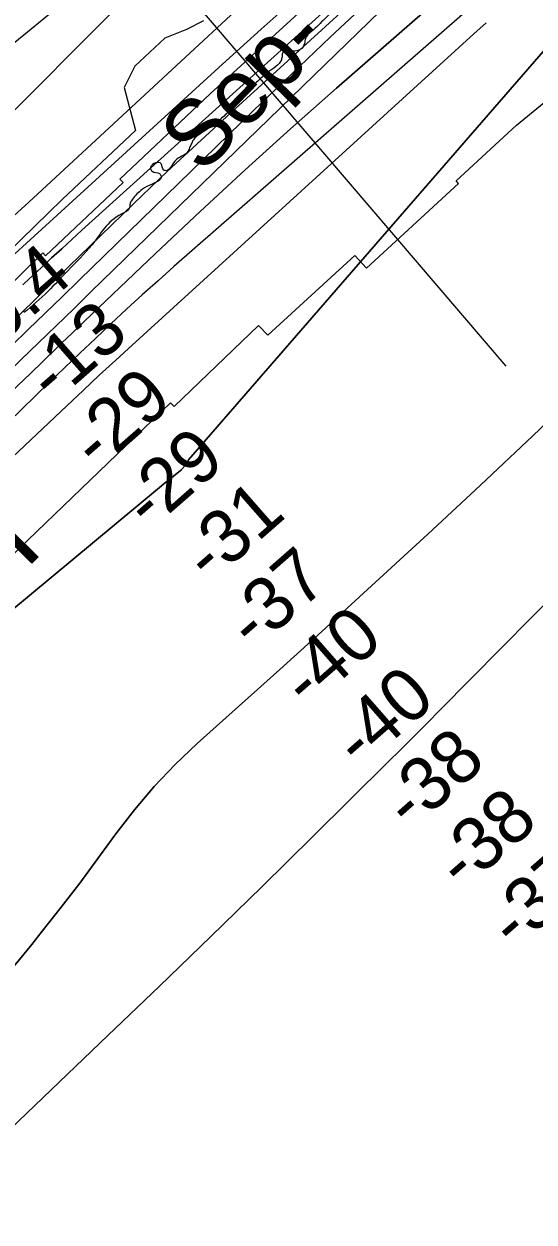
# Model space of a CAD drawing. Extents: x 3419139 to 3457078, y 540382 to 565875.
# Drawn here: x 3451925 to 3452566, y 547868 to 549375 of the extents above; entities that cross this region are included whole.
import ezdxf

# ---------------------------------------------------------------- set-up
doc = ezdxf.new("R2010")
doc.units = 0
for name, color, linetype in [('V-RIVR-EDGE', 7, 'Continuous'), ('V-RIVR-IDEN', 7, 'Continuous'), ('V-RIVR-RANG', 7, 'Continuous'), ('V-RRAP-RVMT', 7, 'Continuous'), ('V-RRAP-RVMT-IDEN', 7, 'Continuous'), ('V-SITE-VEGE', 7, 'Continuous'), ('V-TOPO-DPTH', 7, 'Continuous'), ('V-TOPO-MINR', 7, 'Continuous'), ('V-TOPO-WATR', 7, 'Continuous'), ('V-WETL-SWMP', 7, 'Continuous')]:
    doc.layers.add(name, color=color, linetype=linetype)

msp = doc.modelspace()

# ---------------------------------------------------------------- linework, layer by layer
at = {"layer": 'V-RIVR-EDGE'}
msp.add_spline([(3452565, 549632.1), (3452565.8, 549625.9), (3452563.7, 549618.5), (3452554.6, 549606.1), (3452547.2, 549600.4), (3452538.9, 549595.9), (3452524.5, 549586.4), (3452523.6, 549582.7), (3452524.4, 549578.2), (3452515.8, 549570.4), (3452499.6, 549558.9), (3452491, 549550.6), (3452475.2, 549530), (3452462.9, 549521.8), (3452457.1, 549517.3), (3452450, 549512.4), (3452445.1, 549511.1), (3452443.9, 549509.1), (3452445.1, 549506.2), (3452435.2, 549495.9), (3452420.7, 549482.3), (3452414.1, 549476.2), (3452409.5, 549472.9), (3452405.8, 549470), (3452404.2, 549467.9), (3452400, 549461.4), (3452394.6, 549457.7), (3452387.6, 549454.8), (3452379.8, 549447), (3452351.7, 549422.3), (3452344.2, 549414.5), (3452341.3, 549414.5), (3452336.8, 549417.4), (3452332.7, 549417.4), (3452327.3, 549414.9), (3452324.8, 549411.6), (3452327.3, 549406.3), (3452327.3, 549403), (3452324.8, 549400.1), (3452317.4, 549393.9), (3452303.3, 549381.2), (3452286.8, 549365.5), (3452278.9, 549356.5), (3452277.7, 549350.3), (3452273.1, 549342.9), (3452262.8, 549340.4), (3452255, 549340.1), (3452250.4, 549338.8), (3452249.6, 549334.7), (3452248.7, 549329.8), (3452231.8, 549314.1), (3452217.3, 549301.4), (3452203.7, 549290.3), (3452185.5, 549268.1), (3452173.5, 549256.1), (3452162.4, 549247.1), (3452149.5, 549238.5), (3452142.5, 549233.5), (3452138, 549229), (3452135.9, 549224.9), (3452133.8, 549220.3), (3452131.3, 549214.6), (3452114.8, 549202.2), (3452102.4, 549190.3), (3452100.8, 549191.1), (3452097.5, 549199), (3452094.6, 549200.6), (3452086.8, 549198.2), (3452084.3, 549194.5), (3452084.3, 549192.8), (3452086.3, 549189.5), (3452095.4, 549186.6), (3452097.4, 549183.3), (3452082.6, 549171.8), (3452071.8, 549165.2), (3452060.3, 549152.5), (3452058.2, 549147.9), (3452057.8, 549143.8), (3452047.4, 549135.6), (3452010.6, 549096.9), (3451980, 549064.4), (3451955.2, 549038.5), (3451925, 549011.8)], degree=3, dxfattribs=at)
at = {"layer": 'V-RIVR-RANG'}
msp.add_line((3451920.2, 549659), (3452531, 548944.4), dxfattribs=at)
at = {"layer": 'V-RRAP-RVMT'}
for p, q in [((3452279.9, 549397.3), (3452159.3, 549286.7)), ((3452544.5, 549247.3), (3452684.8, 549364)), ((3452159.3, 549286.7), (3452045.7, 549179.8)), ((3452468.6, 549177.6), (3452544.5, 549247.3)), ((3452045.7, 549179.8), (3452049.8, 549175.4)), ((3452471.5, 549174), (3452468.6, 549177.6)), ((3452049.8, 549175.4), (3451952.3, 549083.3)), ((3452355.7, 549067.6), (3452471.5, 549174)), ((3451948.9, 549086.9), (3451634.9, 548778.5)), ((3451952.3, 549083.3), (3451948.9, 549086.9)), ((3452231.6, 548983.5), (3452341.2, 549083.6)), ((3452341.2, 549083.6), (3452355.7, 549067.6)), ((3452114, 548893.7), (3452220, 548995.4)), ((3452220, 548995.4), (3452231.6, 548983.5)), ((3451907.2, 548704), (3452109.3, 548898.4)), ((3452109.3, 548898.4), (3452114, 548893.7))]:
    msp.add_line(p, q, dxfattribs=at)
at = {"layer": 'V-SITE-VEGE'}
msp.add_lwpolyline([(3452150.8, 549378.5), (3452129.3, 549367.7), (3452102.3, 549356.9), (3452064.5, 549321.8), (3452051, 549294.8), (3452065.3, 549240.7), (3451973.5, 549154.4), (3451852.5, 549036.7)], dxfattribs=at)
at = {"layer": 'V-TOPO-DPTH'}
for points in [[(3451923.7, 549046.7), (3451925.4, 549048.2), (3451947.2, 549068.7), (3451959.8, 549080.5), (3451972.5, 549092.2), (3451985.2, 549103.9), (3451997.9, 549115.5), (3452460, 549533.4)], [(3451909.4, 548912.4), (3451932.7, 548934.9), (3451966.2, 548967.3), (3451972.6, 548973.6), (3451979.1, 548979.8), (3451985.5, 548985.9), (3451992, 548992.1), (3452090.4, 549086.2), (3452146.5, 549139.1), (3452203, 549191.4), (3452260.3, 549243), (3452317.9, 549294.1), (3452505.1, 549457.4)], [(3452505.1, 549457.4), (3452317.9, 549294.1), (3452260.3, 549243), (3452203, 549191.4), (3452146.5, 549139.1), (3452090.4, 549086.2), (3451992, 548992.1), (3451985.5, 548985.9), (3451979.1, 548979.8), (3451972.6, 548973.6), (3451966.2, 548967.3), (3451932.7, 548934.9), (3451909.4, 548912.4)], [(3451909.1, 548969.6), (3451930.4, 548990.4), (3451951.7, 549011.1), (3451973, 549031.8), (3451994.3, 549052.5), (3452213.6, 549265.8), (3452261.7, 549312.2), (3452310.2, 549358.2), (3452359.1, 549403.9)], [(3452359.1, 549403.9), (3452310.2, 549358.2), (3452261.7, 549312.2), (3452213.6, 549265.8), (3451994.3, 549052.5), (3451973, 549031.8), (3451951.7, 549011.1), (3451930.4, 548990.4), (3451909.1, 548969.6)], [(3452506.1, 549376.3), (3452490.8, 549362.5), (3452061.1, 548971), (3452040.4, 548952.1), (3452019.8, 548933), (3451999.3, 548913.9), (3451978.8, 548894.7), (3451858, 548780.6), (3451777.3, 548704.1), (3451696.7, 548627.5), (3451616.3, 548550.7), (3451536.1, 548473.8), (3451383.4, 548326.9), (3451370.3, 548314.2), (3451357.3, 548301.4), (3451344.4, 548288.6), (3451331.5, 548275.7), (3451219.3, 548162.4), (3451150.7, 548092.5), (3451082.5, 548022.2), (3451014.9, 547951.4), (3450947.7, 547880.1), (3450807.6, 547730.3)], [(3450807.6, 547730.3), (3450947.7, 547880.1), (3451014.9, 547951.4), (3451082.5, 548022.2), (3451150.7, 548092.5), (3451219.3, 548162.4), (3451331.5, 548275.7), (3451344.4, 548288.6), (3451357.3, 548301.4), (3451370.3, 548314.2), (3451383.4, 548326.9), (3451536.1, 548473.8), (3451616.3, 548550.7), (3451696.7, 548627.5), (3451777.3, 548704.1), (3451858, 548780.6), (3451978.8, 548894.7), (3451999.3, 548913.9), (3452019.8, 548933), (3452040.4, 548952.1), (3452061.1, 548971), (3452490.8, 549362.5), (3452506.1, 549376.3)], [(3452608.4, 549375.3), (3452132.1, 548826.6), (3452131, 548824.9), (3452129.6, 548822.2), (3452127.9, 548819.7), (3452124.4, 548815.6), (3452123.3, 548814.3), (3452122.7, 548813.8), (3452122, 548813.2), (3452113.2, 548806.1), (3452108.1, 548802.1), (3452103.1, 548798), (3452098, 548793.8), (3452093, 548789.7), (3451451.5, 548256.9), (3451435.7, 548243.3), (3451420.2, 548229.3), (3451405.3, 548214.7), (3450980.5, 547563.8)], [(3450980.5, 547563.8), (3451405.3, 548214.7), (3451420.2, 548229.3), (3451435.7, 548243.3), (3451451.5, 548256.9), (3452093, 548789.7), (3452098, 548793.8), (3452103.1, 548798), (3452108.1, 548802.1), (3452113.2, 548806.1), (3452122, 548813.2), (3452122.7, 548813.8), (3452123.3, 548814.3), (3452124.4, 548815.6), (3452127.9, 548819.7), (3452129.6, 548822.2), (3452131, 548824.9), (3452132.1, 548826.6), (3452608.4, 549375.3)], [(3452630.1, 548919.3), (3452564.8, 548856.7), (3452499, 548794.7), (3452432.8, 548733.2), (3452352.1, 548658.9), (3452325.9, 548634.9), (3452299.6, 548610.9), (3452273.3, 548587), (3452246.9, 548563.2), (3452142.8, 548470), (3452115.2, 548443.5), (3452088.7, 548415.9), (3452064.1, 548386.6), (3452040.7, 548356.3), (3452018.1, 548325.3), (3451995.1, 548294.5), (3451971.7, 548264), (3451948.1, 548233.8), (3451935, 548217.4), (3451904.1, 548179.5)], [(3451904.1, 548179.5), (3451935, 548217.4), (3451948.1, 548233.8), (3451971.7, 548264), (3451995.1, 548294.5), (3452018.1, 548325.3), (3452040.7, 548356.3), (3452064.1, 548386.6), (3452088.7, 548415.9), (3452115.2, 548443.5), (3452142.8, 548470), (3452246.9, 548563.2), (3452273.3, 548587), (3452299.6, 548610.9), (3452325.9, 548634.9), (3452352.1, 548658.9), (3452432.8, 548733.2), (3452499, 548794.7), (3452564.8, 548856.7), (3452630.1, 548919.3)], [(3451491.6, 547070.7), (3451678.4, 547279.4), (3451704.9, 547310.2), (3451730.7, 547341.5), (3451755.4, 547373.8), (3451778.4, 547434.8), (3451737.8, 547821.1), (3451747, 547830.6), (3451756.3, 547840), (3451765.8, 547849.4), (3451775.3, 547858.6), (3452030.7, 548102.6), (3452095.5, 548164.7), (3452160, 548227.1), (3452224.1, 548289.8), (3452288.1, 548352.8), (3452382.6, 548446.3), (3452399.1, 548462.7), (3452415.5, 548479.1), (3452432, 548495.6), (3452448.3, 548512.1), (3452640, 548706.1)], [(3452640, 548706.1), (3452448.3, 548512.1), (3452432, 548495.6), (3452415.5, 548479.1), (3452399.1, 548462.7), (3452382.6, 548446.3), (3452288.1, 548352.8), (3452224.1, 548289.8), (3452160, 548227.1), (3452095.5, 548164.7), (3452030.7, 548102.6), (3451775.3, 547858.6), (3451765.8, 547849.4), (3451756.3, 547840), (3451747, 547830.6), (3451737.8, 547821.1), (3451778.4, 547434.8), (3451755.4, 547373.8), (3451730.7, 547341.5), (3451704.9, 547310.2), (3451678.4, 547279.4), (3451491.6, 547070.7)]]:
    msp.add_lwpolyline(points, dxfattribs=at)
at = {"layer": 'V-TOPO-MINR'}
for points in [[(3452512.9, 549526.9), (3452009.6, 549038.2), (3451987.6, 549016.7), (3451965.5, 548995.3), (3451943.4, 548973.9), (3451921.3, 548952.5), (3451866.4, 548899.2), (3451816.8, 548851.2), (3451767.2, 548803.2), (3451717.6, 548755.2), (3451667.9, 548707.3), (3451317.9, 548369.9), (3451313.2, 548365.3), (3451308.5, 548360.8), (3451303.8, 548356.2), (3451299.1, 548351.6), (3451249, 548302.5), (3451219.4, 548273.3), (3451189.9, 548243.9), (3451160.7, 548214.3), (3451131.5, 548184.6), (3450732.2, 547775.6)], [(3452479.5, 549531.8), (3452190.5, 549268.2), (3452147.7, 549228.8), (3452105.1, 549189.1), (3452063, 549148.9), (3452021.1, 549108.5), (3451995.6, 549083.6), (3451966.6, 549055.4), (3451937.7, 549027.2), (3451908.8, 548998.9)], [(3452460, 549533.4), (3451997.9, 549115.5), (3451985.2, 549103.9), (3451972.5, 549092.2), (3451959.8, 549080.5), (3451947.2, 549068.7), (3451925.4, 549048.2), (3451923.7, 549046.7)], [(3452552.1, 549453.2), (3452113.6, 549069.7), (3452093.6, 549051.9), (3452073.6, 549034.1), (3452053.9, 549016), (3452034.3, 548997.8), (3452014.8, 548979.4), (3451995.4, 548961), (3451976.1, 548942.4), (3451956.9, 548923.8), (3451615.6, 548591.4), (3451569.7, 548546.6), (3451523.8, 548501.8), (3451477.9, 548456.9), (3451432, 548412.1), (3451385.4, 548366.5), (3451362.9, 548344.3), (3451340.4, 548322.1), (3451318.1, 548299.9), (3451295.7, 548277.6), (3450897, 547877.4), (3450871, 547851.2)], [(3452505.1, 549457.4), (3452317.9, 549294.1), (3452260.3, 549243), (3452203, 549191.4), (3452146.5, 549139.1), (3452090.4, 549086.2), (3451992, 548992.1), (3451985.5, 548985.9), (3451979.1, 548979.8), (3451972.6, 548973.6), (3451966.2, 548967.3), (3451932.7, 548934.9), (3451909.4, 548912.4)], [(3451837.4, 549190.9), (3451935.7, 549288.9), (3451995.9, 549349.5), (3452055.9, 549410.3)], [(3452272.3, 549412.1), (3452223.3, 549368.4), (3452174.6, 549324.3), (3451928.3, 549099.2), (3451913.5, 549085.6)], [(3452190.7, 549390.9), (3452128.2, 549333), (3452065.7, 549275.2), (3451931, 549150.8), (3451903, 549125), (3451875.1, 549099), (3451847.2, 549073.1), (3451819.3, 549047.1), (3451521.1, 548768.1), (3451469.2, 548719.2), (3451417.6, 548670.1), (3451366.4, 548620.6), (3451315.4, 548570.8), (3451243.6, 548500.2), (3451228.7, 548485.5), (3451213.7, 548471), (3451198.6, 548456.5), (3451183.4, 548442.2), (3450740.1, 548024.2), (3450715, 548000.7), (3450689.8, 547977.3), (3450664.3, 547954.2), (3450638.8, 547931.2)], [(3452506.1, 549376.3), (3452490.8, 549362.5), (3452061.1, 548971), (3452040.4, 548952.1), (3452019.8, 548933), (3451999.3, 548913.9), (3451978.8, 548894.7), (3451858, 548780.6), (3451777.3, 548704.1), (3451696.7, 548627.5), (3451616.3, 548550.7), (3451536.1, 548473.8), (3451383.4, 548326.9), (3451370.3, 548314.2), (3451357.3, 548301.4), (3451344.4, 548288.6), (3451331.5, 548275.7), (3451219.3, 548162.4), (3451150.7, 548092.5), (3451082.5, 548022.2), (3451014.9, 547951.4), (3450947.7, 547880.1), (3450807.6, 547730.3)], [(3452608.4, 549375.3), (3452132.1, 548826.6), (3452131, 548824.9), (3452129.6, 548822.2), (3452127.9, 548819.7), (3452124.4, 548815.6), (3452123.3, 548814.3), (3452122.7, 548813.8), (3452122, 548813.2), (3452113.2, 548806.1), (3452108.1, 548802.1), (3452103.1, 548798), (3452098, 548793.8), (3452093, 548789.7), (3451451.5, 548256.9), (3451435.7, 548243.3), (3451420.2, 548229.3), (3451405.3, 548214.7), (3450980.5, 547563.8)], [(3451904.1, 548179.5), (3451935, 548217.4), (3451948.1, 548233.8), (3451971.7, 548264), (3451995.1, 548294.5), (3452018.1, 548325.3), (3452040.7, 548356.3), (3452064.1, 548386.6), (3452088.7, 548415.9), (3452115.2, 548443.5), (3452142.8, 548470), (3452246.9, 548563.2), (3452273.3, 548587), (3452299.6, 548610.9), (3452325.9, 548634.9), (3452352.1, 548658.9), (3452432.8, 548733.2), (3452499, 548794.7), (3452564.8, 548856.7), (3452630.1, 548919.3)], [(3451491.6, 547070.7), (3451678.4, 547279.4), (3451704.9, 547310.2), (3451730.7, 547341.5), (3451755.4, 547373.8), (3451778.4, 547434.8), (3451737.8, 547821.1), (3451747, 547830.6), (3451756.3, 547840), (3451765.8, 547849.4), (3451775.3, 547858.6), (3452030.7, 548102.6), (3452095.5, 548164.7), (3452160, 548227.1), (3452224.1, 548289.8), (3452288.1, 548352.8), (3452382.6, 548446.3), (3452399.1, 548462.7), (3452415.5, 548479.1), (3452432, 548495.6), (3452448.3, 548512.1), (3452640, 548706.1)]]:
    msp.add_lwpolyline(points, dxfattribs=at)
at = {"layer": 'V-TOPO-WATR'}
msp.add_lwpolyline([(3452359.1, 549403.9), (3452310.2, 549358.2), (3452261.7, 549312.2), (3452213.6, 549265.8), (3451994.3, 549052.5), (3451973, 549031.8), (3451951.7, 549011.1), (3451930.4, 548990.4), (3451909.1, 548969.6)], dxfattribs=at)
at = {"layer": 'V-WETL-SWMP'}
msp.add_lwpolyline([(3451977.8, 549403.7), (3451904.5, 549343.7)], dxfattribs=at)

# ---------------------------------------------------------------- texts
at = {"layer": 'V-RIVR-IDEN'}
msp.add_text('Sep-', height=83, rotation=45.9011, dxfattribs=at).set_placement((3452148.8, 549184.1))
at = {"layer": 'V-RIVR-RANG'}
for s, rotation, p in [('10.4', 40.9383, (3451857.4, 548938.6)), ('-13', 41.2263, (3451961.9, 548896.4)), ('-29', 41.2263, (3452017.5, 548812.2)), ('-29', 41.2263, (3452083.2, 548736.8)), ('-31', 41.2263, (3452158.8, 548670.1)), ('-37', 41.2263, (3452213.8, 548585.4)), ('-40', 41.2263, (3452281.9, 548512.1)), ('-40', 41.2263, (3452347.6, 548436.7)), ('-38', 41.2263, (3452410.8, 548359.1)), ('-38', 41.2263, (3452476.5, 548283.7)), ('-37', 41.2263, (3452542.4, 548208.5))]:
    msp.add_text(s, height=67, rotation=rotation, dxfattribs=at).set_placement(p)
at = {"layer": 'V-RRAP-RVMT-IDEN'}
msp.add_text('BELMONT', height=100, rotation=45.6111, dxfattribs=at).set_placement((3451515.9, 548267.4))

doc.saveas('drawing.dxf')
